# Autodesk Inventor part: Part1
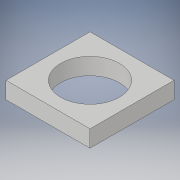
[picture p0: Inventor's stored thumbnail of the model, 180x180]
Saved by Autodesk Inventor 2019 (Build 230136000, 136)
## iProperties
Created: 2019-07
Part Number: Part1
Material: Generic
Document SubType Name: Modeling
Designer: Synergysoft
Density: 1 g/cm^3
Appearance: Default
Author: Synergysoft
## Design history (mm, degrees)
sketch "Sketch1"
  geometry: L1 (25, 25)-(-25, 25); L2 (-25, 25)-(-25, -25); L3 (-25, -25)-(25, -25); L4 (25, -25)-(25, 25); L5 (25, 25)-(-25, -25); L6 (-25, 25)-(25, -25); 3 further points
  constraints: 12 end point, 3 midpoint, 2 parallel, 1 coincident, 1 horizontal, 1 perpendicular
  dimensions: "d0" = 50 distance of L3.end L2.end; "d1" = 50 distance of L2.end L1.end
sketch "Sketch2"
  geometry: C1 r 17.5 at (0, 0); 1 further point
  constraints: 1 centre point, 1 coincident
  dimensions: "d5" = 35 diameter of C1
extrude "Extrusion2" new body sketch "Sketch1" distance "d6" = 10; taper "d7" = 0 deg
extrude "Extrusion3" cut sketch "Sketch2" distance "d8" = 10; taper "d9" = 0 deg
body "Solid2"
